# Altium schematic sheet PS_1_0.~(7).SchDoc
size A4
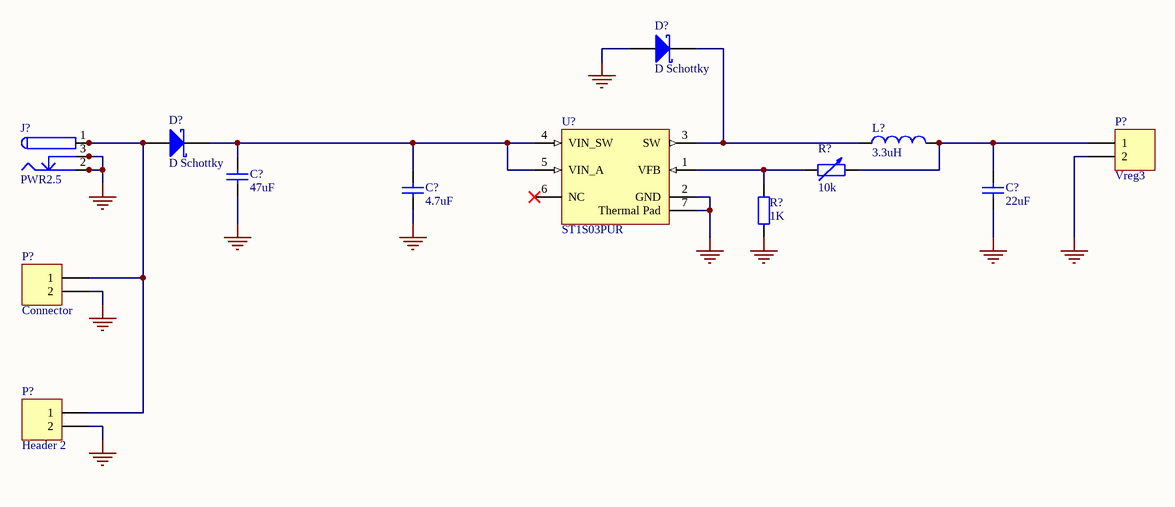
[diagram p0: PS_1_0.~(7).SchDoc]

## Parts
(Parts that share a designator on the sheet are numbered #1, #2 ... from top to bottom, then left to right.)
C?#1  47uF  [C0805]
C?#2  4.7uF  [C0805]
C?#3  22uF  [C0805]
D?#1  D Schottky  [SMB]
D?#2  D Schottky  [SMB]
J?  PWR2.5  [KLD-0202]
L?  3.3uH  [0402-A]
P?#1  Vreg3  [HDR1X2]
P?#2  Connector  [L_ZAC]
P?#3  Header 2  [HDR1X2]
R?#1  10k  [AXIAL-0.6]
R?#2  1K  [0603]
U?  ST1S03PUR  [DFN6D_M]

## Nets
GND: C?#1.2 C?#2.2 C?#3.2 D?#1.1(A) J?.2 J?.2A J?.2B J?.3 J?.3A J?.3B P?#1.2 P?#2.2 P?#3.2 R?#2.1 U?.2(GND) U?.7(Thermal_Pad)
NetC?#1_1: C?#1.1 C?#2.1 D?#2.2(K) U?.4(VIN_SW) U?.5(VIN_A)
NetC?#3_1: C?#3.1 L?.2 P?#1.1 R?#1.2
NetD?#1_2: D?#1.2(K) L?.1 U?.3(SW)
NetD?#2_1: D?#2.1(A) J?.1 J?.1A J?.1B P?#2.1 P?#3.1
NetR?#1_1: R?#1.1 R?#2.2 U?.1(VFB)

Not connected (* = marked no-connect by the designer): U? 6(NC)*

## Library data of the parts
C?#1-C?#3 = Cap Semi: Capacitor (Semiconductor SIM Model)
D?#1 D?#2 = D Schottky: Schottky Diode
J? = PWR2.5: Low Voltage Power Supply Connector
L? = Inductor: Code_IEC: 1005
P?#1-P?#3 = Header 2: Header, 2-Pin
R?#1 = Res Adj2: Variable Resistor; Set Position: 0.5
R?#2 = Res2: Resistor
U? = ST1S03PUR: 1.5 A, 1.5 MHz adjustable, step-down switching regulator, DFN6D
